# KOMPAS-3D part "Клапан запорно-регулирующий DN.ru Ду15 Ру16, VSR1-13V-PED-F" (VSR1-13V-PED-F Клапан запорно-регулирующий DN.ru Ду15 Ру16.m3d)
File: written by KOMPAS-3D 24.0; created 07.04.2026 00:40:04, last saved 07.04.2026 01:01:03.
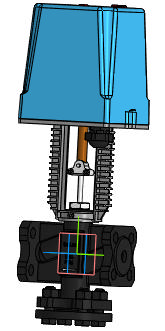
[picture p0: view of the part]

Document properties: Автор: R2D2; Полное имя файла: VSR1-13V-PED-F Клапан запорно-регулирующий DN.ru Ду15 Ру16.cdw

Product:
- Part/product: Клапан запорно-регулирующий DN.ru Ду15 Ру16  | designation VSR1-13V-PED-F
    Масса: 6.1
    Раздел спецификации: Прочие изделия
    Форматы листов документа: A3
    Примечание: D090-02886

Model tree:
1. Операция без истории:1  (labels: SHAPEOBJECT3D_ATTR_BUTT)

Expressions: VSR1-13V-PED-F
